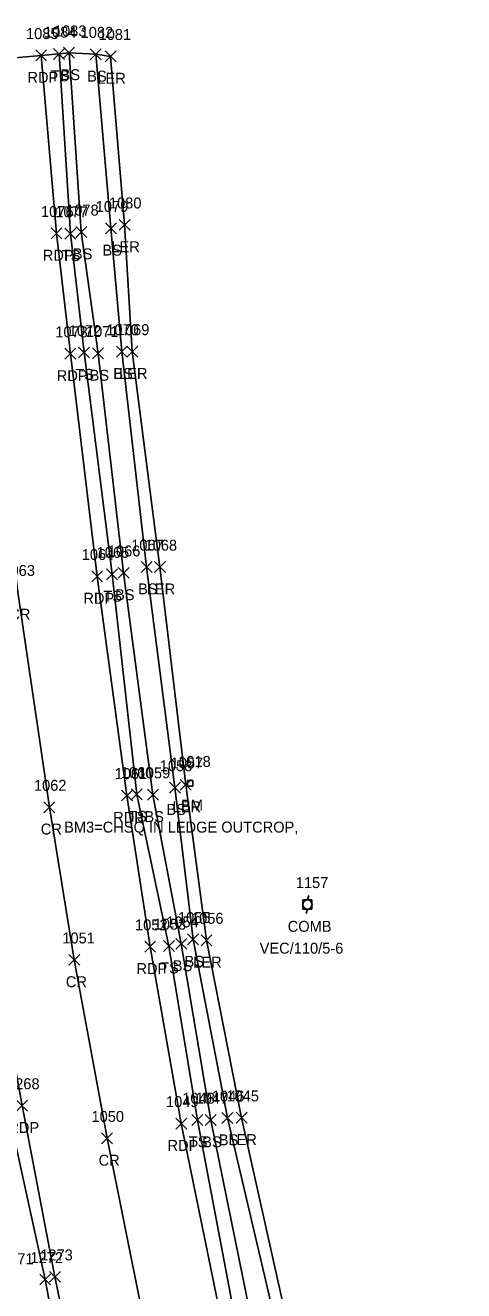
# Model space of a CAD drawing. Extents: x 1512665 to 1513714, y 110636 to 112816.
# Drawn here: x 1513207.4 to 1513287.6, y 110908.3 to 111139.7 of the extents above; entities that cross this region are included whole.
import ezdxf

# ---------------------------------------------------------------- set-up
doc = ezdxf.new("R2010")
doc.units = 0
for name, color, linetype in [('C_A', 7, 'Continuous'), ('C_C', 7, 'Continuous'), ('C_I', 7, 'Continuous'), ('CPBM', 7, 'Continuous'), ('L_A', 7, 'Continuous'), ('L_I', 7, 'Continuous'), ('L_TIC', 7, 'Continuous'), ('LARO', 7, 'Continuous'), ('LELB', 7, 'Continuous'), ('LSOGP', 7, 'Continuous'), ('P_A', 7, 'Continuous'), ('P_I', 7, 'Continuous'), ('P_TIC', 7, 'Continuous'), ('PET', 7, 'Continuous'), ('PRC', 7, 'Continuous'), ('U_A', 7, 'Continuous'), ('U_C', 7, 'Continuous'), ('U_I', 7, 'Continuous'), ('UP', 7, 'Continuous')]:
    doc.layers.add(name, color=color, linetype=linetype)

msp = doc.modelspace()

# ---------------------------------------------------------------- linework, layer by layer
at = {"layer": 'CPBM'}
for p, q in [((1513237.08, 111000.54), (1513237.08, 111001.54)), ((1513237.08, 111001.54), (1513238.08, 111001.54)), ((1513238.08, 111000.54), (1513237.08, 111000.54)), ((1513237.58, 111001.04), (1513237.58, 111001.04)), ((1513237.58, 111001.04), (1513237.58, 111001.04)), ((1513238.08, 111001.54), (1513238.08, 111000.54))]:
    msp.add_line(p, q, dxfattribs=at)
at = {"layer": 'L_TIC'}
for points in [[(1513212.58, 111133.44), (1513214.58, 111135.44)], [(1513214.58, 111133.44), (1513212.58, 111135.44)], [(1513214.41, 111133.66), (1513216.41, 111135.66)], [(1513216.41, 111133.66), (1513214.41, 111135.66)], [(1513219.29, 111133.39), (1513221.29, 111135.39)], [(1513221.29, 111133.39), (1513219.29, 111135.39)], [(1513222, 111133), (1513224, 111135)], [(1513224, 111133), (1513222, 111135)], [(1513214.66, 111100.58), (1513216.66, 111102.58)], [(1513216.66, 111100.58), (1513214.66, 111102.58)], [(1513216.65, 111100.89), (1513218.65, 111102.89)], [(1513218.65, 111100.89), (1513216.65, 111102.89)], [(1513222.07, 111101.56), (1513224.07, 111103.56)], [(1513224.07, 111101.56), (1513222.07, 111103.56)], [(1513224.56, 111102.19), (1513226.56, 111104.19)], [(1513226.56, 111102.19), (1513224.56, 111104.19)], [(1513217.14, 111078.84), (1513219.14, 111080.84)], [(1513219.14, 111078.84), (1513217.14, 111080.84)], [(1513219.72, 111078.68), (1513221.72, 111080.68)], [(1513221.72, 111078.68), (1513219.72, 111080.68)], [(1513224.06, 111079), (1513226.06, 111081)], [(1513226.06, 111079), (1513224.06, 111081)], [(1513225.98, 111079.02), (1513227.98, 111081.02)], [(1513227.98, 111079.02), (1513225.98, 111081.02)], [(1513222.28, 111038.29), (1513224.28, 111040.29)], [(1513224.28, 111038.29), (1513222.28, 111040.29)], [(1513224.38, 111038.55), (1513226.38, 111040.55)], [(1513226.38, 111038.55), (1513224.38, 111040.55)], [(1513228.59, 111039.61), (1513230.59, 111041.61)], [(1513230.59, 111039.61), (1513228.59, 111041.61)], [(1513231.04, 111039.6), (1513233.04, 111041.6)], [(1513233.04, 111039.6), (1513231.04, 111041.6)], [(1513233.78, 110999.27), (1513235.78, 111001.27)], [(1513235.78, 110999.27), (1513233.78, 111001.27)], [(1513235.76, 110999.77), (1513237.76, 111001.77)], [(1513237.76, 110999.77), (1513235.76, 111001.77)], [(1513226.79, 110998.01), (1513228.79, 111000.01)], [(1513228.79, 110998.01), (1513226.79, 111000.01)], [(1513229.75, 110997.96), (1513231.75, 110999.96)], [(1513231.75, 110997.96), (1513229.75, 110999.96)], [(1513234.95, 110970.69), (1513236.95, 110972.69)], [(1513236.95, 110970.69), (1513234.95, 110972.69)], [(1513237.1, 110971.49), (1513239.1, 110973.49)], [(1513239.1, 110971.49), (1513237.1, 110973.49)], [(1513239.55, 110971.35), (1513241.55, 110973.35)], [(1513241.55, 110971.35), (1513239.55, 110973.35)], [(1513232.67, 110970.28), (1513234.67, 110972.28)], [(1513234.67, 110970.28), (1513232.67, 110972.28)], [(1513237.9, 110938.46), (1513239.9, 110940.46)], [(1513239.9, 110938.46), (1513237.9, 110940.46)], [(1513240.33, 110938.47), (1513242.33, 110940.47)], [(1513242.33, 110938.47), (1513240.33, 110940.47)], [(1513243.37, 110938.84), (1513245.37, 110940.84)], [(1513245.37, 110938.84), (1513243.37, 110940.84)], [(1513245.98, 110938.88), (1513247.98, 110940.88)], [(1513247.98, 110938.88), (1513245.98, 110940.88)], [(1513210.03, 110909.3), (1513212.03, 110911.3)], [(1513212.03, 110909.3), (1513210.03, 110911.3)]]:
    msp.add_lwpolyline(points, dxfattribs=at)
at = {"layer": 'LARO'}
msp.add_lwpolyline([(1513287.62, 110771.43), (1513278.66, 110804.35), (1513266.83, 110847.25), (1513263.56, 110857.54), (1513257.52, 110892.59), (1513246.98, 110939.88), (1513240.55, 110972.35), (1513236.76, 111000.77), (1513232.04, 111040.6), (1513226.98, 111080.02), (1513225.56, 111103.19), (1513223, 111134)], dxfattribs=at)
at = {"layer": 'LELB'}
for points in [[(1513281.07, 110769.49), (1513272.18, 110804.3), (1513261.37, 110845.09), (1513250.96, 110892.05), (1513241.33, 110939.47), (1513235.95, 110971.69), (1513230.75, 110998.96), (1513225.38, 111039.55), (1513220.72, 111079.68), (1513217.65, 111101.89), (1513215.41, 111134.66)], [(1513279.66, 110769.09), (1513269.36, 110804.1), (1513258.58, 110845.03), (1513248.03, 110891.08), (1513238.9, 110939.46), (1513233.67, 110971.28), (1513227.79, 110999.01), (1513223.28, 111039.29), (1513218.14, 111079.84), (1513215.66, 111101.58), (1513213.58, 111134.44)], [(1513285.37, 110770.76), (1513275.94, 110804.91), (1513264.13, 110845.89), (1513261.43, 110856.02), (1513255.56, 110892.3), (1513244.37, 110939.84), (1513238.1, 110972.49), (1513234.78, 111000.27), (1513229.59, 111040.61), (1513225.06, 111080), (1513223.07, 111102.56), (1513220.29, 111134.39)], [(1513199.08, 110968.9), (1513204.16, 110941.9), (1513211.03, 110910.3), (1513214.77, 110890.32), (1513221.11, 110860.79), (1513225.66, 110841.85), (1513234.54, 110808.65), (1513239.21, 110788.36), (1513247.66, 110759.74)]]:
    msp.add_lwpolyline(points, dxfattribs=at)
at = {"layer": 'LSOGP'}
msp.add_lwpolyline([(1513257.52, 110892.59), (1513246.98, 110939.88), (1513240.55, 110972.34), (1513236.76, 111000.77), (1513232.04, 111040.6), (1513226.98, 111080.02), (1513225.57, 111103.19), (1513223, 111134), (1513220.29, 111134.4), (1513215.41, 111134.65), (1513213.58, 111134.44), (1513210.3, 111134.17), (1513195.74, 111132.86)], dxfattribs=at)
at = {"layer": 'P_TIC'}
for points in [[(1513209.3, 111133.17), (1513211.3, 111135.17)], [(1513211.3, 111133.17), (1513209.3, 111135.17)], [(1513212.11, 111100.63), (1513214.11, 111102.63)], [(1513214.11, 111100.63), (1513212.11, 111102.63)], [(1513214.66, 111078.61), (1513216.66, 111080.61)], [(1513216.66, 111078.61), (1513214.66, 111080.61)], [(1513219.55, 111037.9), (1513221.55, 111039.9)], [(1513221.55, 111037.9), (1513219.55, 111039.9)], [(1513224.99, 110997.82), (1513226.99, 110999.82)], [(1513226.99, 110997.82), (1513224.99, 110999.82)], [(1513210.8, 110995.68), (1513212.8, 110997.68)], [(1513212.8, 110995.68), (1513210.8, 110997.68)], [(1513229.25, 110970.16), (1513231.25, 110972.16)], [(1513231.25, 110970.16), (1513229.25, 110972.16)], [(1513215.37, 110967.76), (1513217.37, 110969.76)], [(1513217.37, 110967.76), (1513215.37, 110969.76)], [(1513205.8, 110941.1), (1513207.8, 110943.1)], [(1513207.8, 110941.1), (1513205.8, 110943.1)], [(1513234.93, 110937.82), (1513236.93, 110939.82)], [(1513236.93, 110937.82), (1513234.93, 110939.82)], [(1513221.37, 110935.12), (1513223.37, 110937.12)], [(1513223.37, 110935.12), (1513221.37, 110937.12)], [(1513211.83, 110909.79), (1513213.83, 110911.79)], [(1513213.83, 110909.79), (1513211.83, 110911.79)]]:
    msp.add_lwpolyline(points, dxfattribs=at)
at = {"layer": 'PET'}
for points in [[(1513276.33, 110768.1), (1513266.56, 110803.7), (1513256.52, 110844.87), (1513245.76, 110890.86), (1513235.93, 110938.82), (1513230.25, 110971.16), (1513225.99, 110998.82), (1513220.55, 111038.9), (1513215.66, 111079.61), (1513213.11, 111101.63), (1513210.3, 111134.17)], [(1513181.78, 111131.32), (1513183.34, 111114.05), (1513184.43, 111101.24), (1513188.03, 111069.41), (1513191.64, 111039.85), (1513195.64, 111010.58), (1513196.78, 111002.78), (1513199.52, 110982.68), (1513202.26, 110966.84), (1513206.8, 110942.1), (1513212.83, 110910.79), (1513216.97, 110890.92), (1513223.71, 110861.11), (1513236.04, 110809.07), (1513241.46, 110788.53), (1513249.29, 110760.24)]]:
    msp.add_lwpolyline(points, dxfattribs=at)
at = {"layer": 'PRC'}
msp.add_lwpolyline([(1513262.69, 110765.32), (1513252.95, 110800.58), (1513242.77, 110841.61), (1513231.95, 110888.45), (1513222.37, 110936.12), (1513216.37, 110968.76), (1513211.8, 110996.68), (1513206.03, 111035.98), (1513201.18, 111077.25), (1513198.65, 111101.07), (1513195.74, 111132.86)], dxfattribs=at)
at = {"layer": 'UP'}
for p, q in [((1513258.2, 110978.06), (1513258.2, 110979.72)), ((1513258.2, 110979.72), (1513259.86, 110979.72)), ((1513259.28, 110980.56), (1513259.03, 110979.72)), ((1513259.86, 110979.72), (1513259.86, 110978.06)), ((1513259.86, 110978.06), (1513258.2, 110978.06)), ((1513258.78, 110977.22), (1513259.03, 110978.06)), ((1513259.03, 110978.89), (1513259.03, 110978.89))]:
    msp.add_line(p, q, dxfattribs=at)
msp.add_circle((1513259.03, 110978.89), 0.833, dxfattribs=at)

# ---------------------------------------------------------------- texts
at = {"layer": 'C_A'}
msp.add_text('BM', height=2, dxfattribs=at).set_placement((1513235.9, 110996.04))
at = {"layer": 'C_C'}
msp.add_text('BM3=CHSQ IN LEDGE OUTCROP,', height=2, dxfattribs=at).set_placement((1513214.5, 110992.04))
at = {"layer": 'C_I'}
msp.add_text('1018', height=2, dxfattribs=at).set_placement((1513235.38, 111004.04))
at = {"layer": 'L_A'}
for s, p in [('TS', (1513211.99, 111129.44)), ('BS', (1513213.85, 111129.66)), ('BS', (1513218.73, 111129.39)), ('LER', (1513220.59, 111129)), ('LER', (1513223.15, 111098.19)), ('TS', (1513214.07, 111096.58)), ('BS', (1513216.09, 111096.89)), ('BS', (1513221.51, 111097.56)), ('TS', (1513216.54, 111074.84)), ('BS', (1513223.5, 111075)), ('LER', (1513224.56, 111075.02)), ('BS', (1513219.16, 111074.68)), ('BS', (1513228.03, 111035.61)), ('LER', (1513229.62, 111035.6)), ('TS', (1513221.69, 111034.29)), ('BS', (1513223.82, 111034.55)), ('TS', (1513226.2, 110994.01)), ('BS', (1513229.19, 110993.96)), ('BS', (1513233.22, 110995.27)), ('LER', (1513234.34, 110995.77)), ('TS', (1513232.08, 110966.28)), ('BS', (1513234.39, 110966.69)), ('BS', (1513236.54, 110967.49)), ('LER', (1513238.13, 110967.35)), ('TS', (1513237.31, 110934.46)), ('BS', (1513239.77, 110934.47)), ('BS', (1513242.81, 110934.84)), ('LER', (1513244.56, 110934.88))]:
    msp.add_text(s, height=2, dxfattribs=at).set_placement(p)
at = {"layer": 'L_I'}
for s, p in [('1084', (1513210.81, 111137.44)), ('1083', (1513212.63, 111137.66)), ('1082', (1513217.52, 111137.39)), ('1081', (1513220.8, 111137)), ('1078', (1513214.87, 111104.89)), ('1079', (1513220.29, 111105.56)), ('1080', (1513222.71, 111106.19)), ('1077', (1513212.89, 111104.58)), ('1072', (1513215.36, 111082.84)), ('1071', (1513218.51, 111082.68)), ('1070', (1513222.21, 111083)), ('1069', (1513224.15, 111083.02)), ('1066', (1513222.5, 111042.55)), ('1067', (1513226.77, 111043.61)), ('1068', (1513229.22, 111043.6)), ('1065', (1513220.46, 111042.29)), ('1058', (1513232.01, 111003.27)), ('1057', (1513233.99, 111003.77)), ('1060', (1513224.88, 111002.01)), ('1059', (1513227.97, 111001.96)), ('1055', (1513235.33, 110975.49)), ('1056', (1513237.72, 110975.35)), ('1053', (1513230.9, 110974.28)), ('1054', (1513233.18, 110974.69)), ('1046', (1513241.54, 110942.84)), ('1045', (1513244.21, 110942.88)), ('1048', (1513236.13, 110942.46)), ('1047', (1513238.56, 110942.47)), ('1271', (1513202.96, 110913.09)), ('1272', (1513208.34, 110913.3))]:
    msp.add_text(s, height=2, dxfattribs=at).set_placement(p)
at = {"layer": 'P_A'}
for s, p in [('RDP', (1513207.79, 111129.17)), ('RDP', (1513210.6, 111096.63)), ('RDP', (1513213.15, 111074.61)), ('RDP', (1513218.03, 111033.9)), ('CR', (1513204.47, 111030.98)), ('RDP', (1513223.48, 110993.82)), ('CR', (1513210.23, 110991.68)), ('RDP', (1513227.74, 110966.16)), ('CR', (1513214.81, 110963.76)), ('RDP', (1513204.29, 110937.1)), ('RDP', (1513233.42, 110933.82)), ('CR', (1513220.81, 110931.12))]:
    msp.add_text(s, height=2, dxfattribs=at).set_placement(p)
at = {"layer": 'P_I'}
for s, p in [('1085', (1513207.53, 111137.17)), ('1076', (1513210.28, 111104.63)), ('1073', (1513212.89, 111082.61)), ('1064', (1513217.73, 111041.9)), ('1063', (1513203.21, 111038.98)), ('1061', (1513223.74, 111001.82)), ('1062', (1513208.98, 110999.68)), ('1052', (1513227.48, 110974.16)), ('1051', (1513214.17, 110971.76)), ('1268', (1513204.06, 110945.1)), ('1049', (1513233.15, 110941.82)), ('1050', (1513219.51, 110939.12)), ('1273', (1513210.14, 110913.79))]:
    msp.add_text(s, height=2, dxfattribs=at).set_placement(p)
at = {"layer": 'U_A'}
msp.add_text('COMB', height=2, dxfattribs=at).set_placement((1513255.42, 110973.89))
at = {"layer": 'U_C'}
msp.add_text('VEC/110/5-6', height=2, dxfattribs=at).set_placement((1513250.28, 110969.89))
at = {"layer": 'U_I'}
msp.add_text('1157', height=2, dxfattribs=at).set_placement((1513256.9, 110981.89))

doc.saveas('drawing.dxf')
